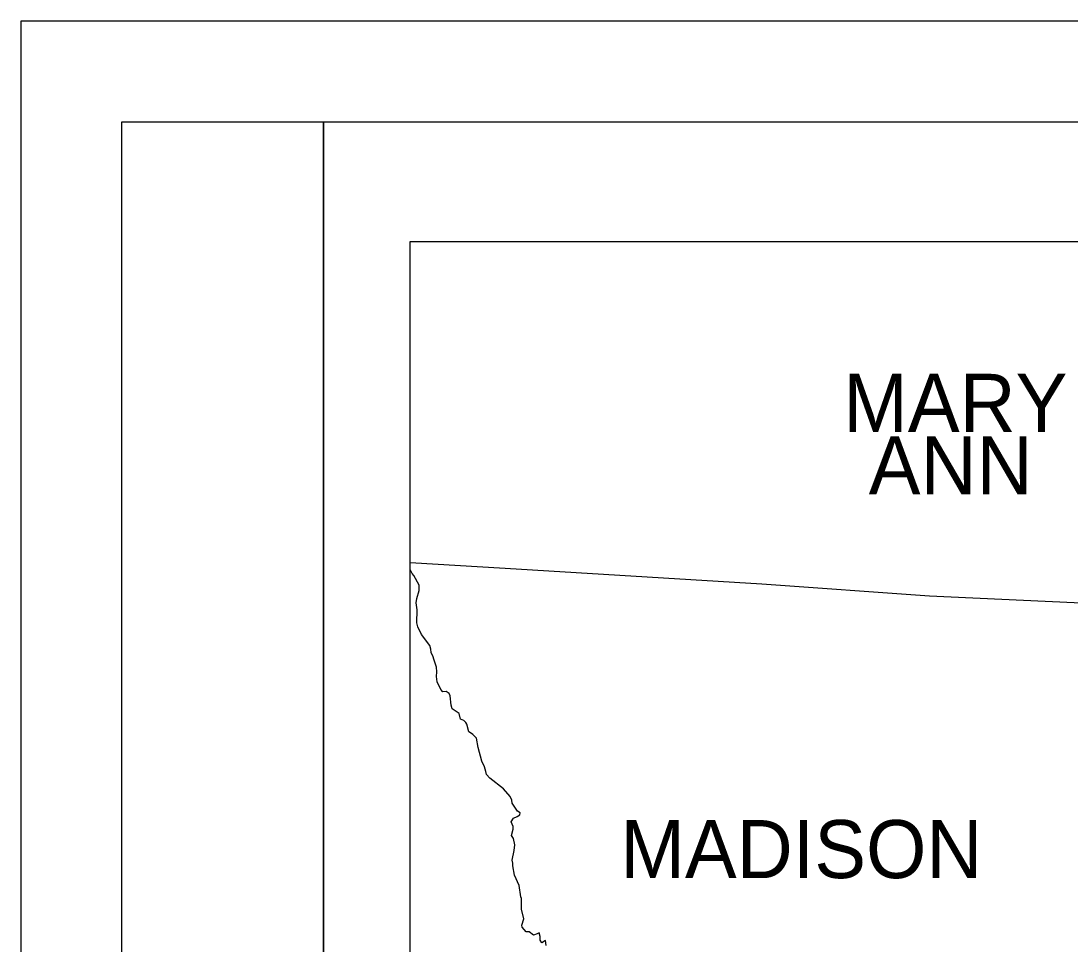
# Model space of a CAD drawing. Extents: x 0 to 34, y 0 to 22.
# Drawn here: x 0 to 5.2, y 17.42 to 22 of the extents above; entities that cross this region are included whole.
import ezdxf

# ---------------------------------------------------------------- set-up
doc = ezdxf.new("R2010")
doc.units = 0
for name, color, linetype in [('GM_X_Minor_River', 7, 'Continuous'), ('GM_X_Township', 7, 'Continuous'), ('GM_X_Township_Text', 7, 'Continuous'), ('SH_Border', 7, 'Continuous'), ('SH_Cut_Line', 7, 'Continuous'), ('SH_Text', 7, 'Continuous')]:
    doc.layers.add(name, color=color, linetype=linetype)

msp = doc.modelspace()

# ---------------------------------------------------------------- linework, layer by layer
at = {"layer": 'GM_X_Minor_River'}
for points in [[(1.9735, 19.1782), (1.9735, 19.205), (1.9465, 19.2536), (1.9395, 19.2626), (1.9289, 19.2825)], [(2.6031, 17.4193), (2.5992, 17.4449), (2.5807, 17.4334), (2.5737, 17.4462), (2.5736, 17.4641), (2.5678, 17.4833), (2.5589, 17.4775), (2.5397, 17.4717), (2.5193, 17.4883), (2.5046, 17.487), (2.4841, 17.5113), (2.4828, 17.5203), (2.4917, 17.5516), (2.4808, 17.5996), (2.48, 17.6521), (2.4775, 17.661), (2.4684, 17.7167), (2.446, 17.7679), (2.4382, 17.8152), (2.4382, 17.828), (2.4344, 17.8421), (2.4445, 17.8907), (2.4477, 17.9182), (2.4412, 17.9508), (2.431, 17.9643), (2.4392, 17.9956), (2.4386, 18.0097), (2.4296, 18.0327), (2.4404, 18.0513), (2.4596, 18.0584), (2.4717, 18.068), (2.4749, 18.0769), (2.4602, 18.0859), (2.4352, 18.1255), (2.4333, 18.1402), (2.4249, 18.1575), (2.391, 18.1965), (2.3245, 18.2495), (2.3078, 18.2674), (2.3033, 18.2815), (2.2975, 18.3045), (2.2841, 18.3339), (2.2661, 18.4011), (2.2583, 18.4472), (2.2398, 18.4657), (2.2283, 18.4734), (2.2193, 18.4791), (2.2097, 18.5162), (2.2052, 18.5245), (2.1943, 18.5354), (2.1777, 18.5418), (2.1725, 18.5699), (2.1367, 18.5929), (2.1322, 18.6108), (2.127, 18.6569), (2.1225, 18.669), (2.1072, 18.678), (2.0906, 18.6767), (2.0803, 18.6875), (2.063, 18.7259), (2.0591, 18.7528), (2.061, 18.7752), (2.0597, 18.7989), (2.0469, 18.8392), (2.0436, 18.85), (2.0328, 18.8711), (2.0321, 18.8884), (2.0269, 18.9057), (1.9847, 18.9607), (1.9661, 18.9984), (1.9622, 19.0189), (1.9628, 19.0828), (1.9589, 19.118), (1.9614, 19.1398), (1.9735, 19.1782)]]:
    msp.add_lwpolyline(points, dxfattribs=at)
at = {"layer": 'GM_X_Township'}
msp.add_lwpolyline([(7.6213, 20.907), (7.5567, 19.4159), (7.5456, 19.0079), (5.686, 19.0954), (4.5032, 19.151), (3.6716, 19.2105), (2.3991, 19.2876), (1.9289, 19.3163)], dxfattribs=at)
at = {"layer": 'SH_Border'}
for points in [[(0.5, 21.5), (1.5, 21.5), (1.5, 0.5), (0.5, 0.5)], [(1.5, 21.5), (33.5, 21.5), (33.5, 0.5), (1.5, 0.5)]]:
    msp.add_lwpolyline(points, close=True, dxfattribs=at)
at = {"layer": 'SH_Cut_Line'}
msp.add_lwpolyline([(0, 0), (34, 0), (34, 22), (0, 22)], close=True, dxfattribs=at)
at = {"layer": 'SH_Text'}
msp.add_lwpolyline([(1.9289, 20.907), (19.068, 20.907), (19.068, 13.067), (1.9289, 13.067)], close=True, dxfattribs=at)

# ---------------------------------------------------------------- texts
at = {"layer": 'GM_X_Township_Text'}
for s, p in [('MARY', (4.0752, 19.9645)), ('ANN', (4.2017, 19.655)), ('MADISON', (2.9704, 17.7538))]:
    msp.add_text(s, height=0.28764, rotation=0, dxfattribs=at).set_placement(p)

doc.saveas('drawing.dxf')
